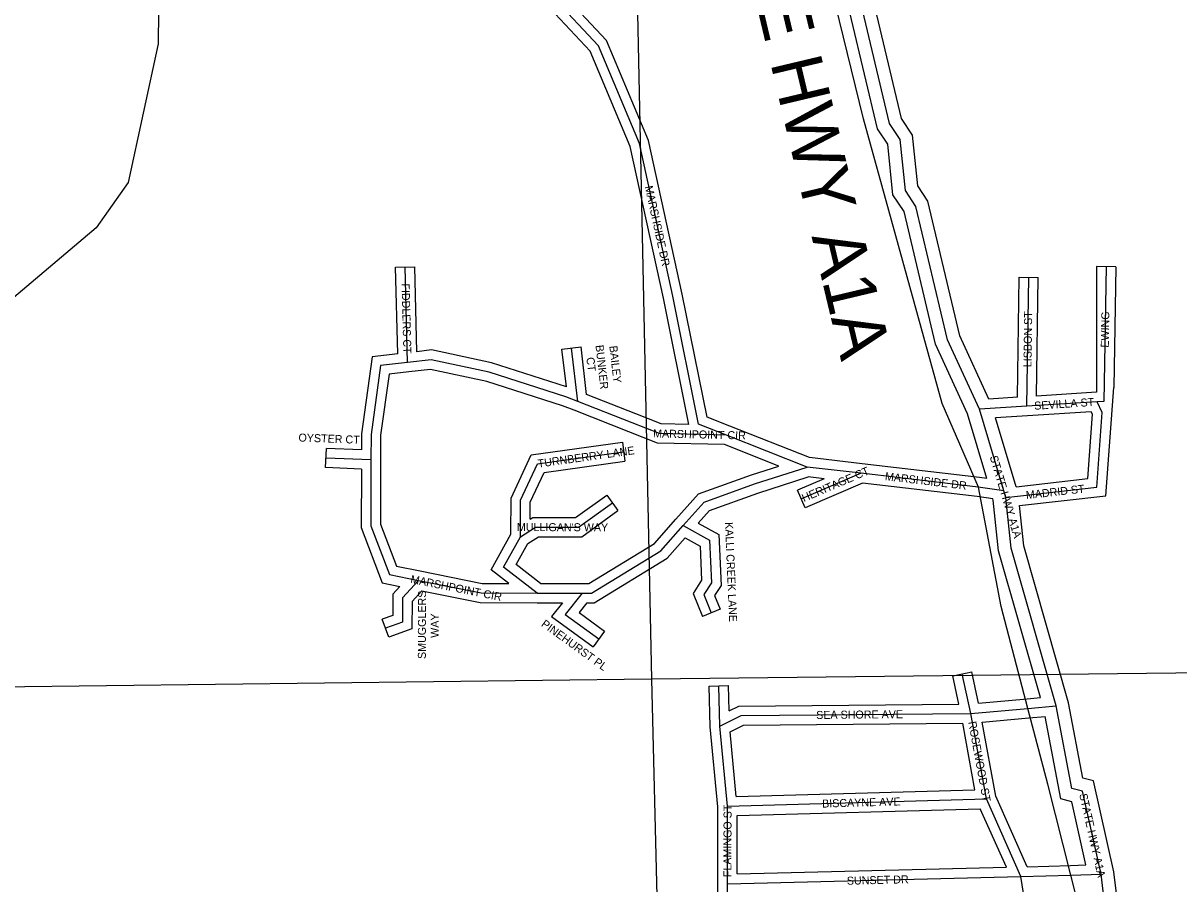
# Model space of a CAD drawing. Extents: x 418523 to 616617, y 1878279 to 2196743.
# Drawn here: x 566432 to 570042, y 1997576 to 2000265 of the extents above; entities that cross this region are included whole.
import ezdxf

# ---------------------------------------------------------------- set-up
doc = ezdxf.new("R2010")
doc.units = 0
for name, color, linetype in [('Level 1', 7, 'Continuous'), ('Level 22', 7, 'Continuous'), ('Level 23', 7, 'Continuous'), ('Level 28', 7, 'Continuous'), ('Level 31', 7, 'Continuous'), ('Level 32', 7, 'Continuous'), ('Level 34', 7, 'Continuous'), ('Level 7', 7, 'Continuous'), ('Level 8', 7, 'Continuous')]:
    doc.layers.add(name, color=color, linetype=linetype)

msp = doc.modelspace()

# ---------------------------------------------------------------- linework, layer by layer
at = {"layer": 'Level 1'}
for p, q in [((568285.081, 2003473.091), (568394.747, 1998215.331)), ((571360.308, 1998250.338), (568394.747, 1998215.331)), ((568394.747, 1998215.331), (565895.431, 1998185.226)), ((568394.747, 1998215.331), (568450.404, 1995887.192))]:
    msp.add_line(p, q, dxfattribs=at)
at = {"layer": 'Level 22'}
for p, q in [((569495.562, 1998804.097), (569419.427, 1999058.473)), ((569501.854, 1998782.99), (569495.562, 1998804.097))]:
    msp.add_line(p, q, dxfattribs=at)
for points in [[(569419.427, 1999058.473), (569319.74, 1999275.448), (569220.845, 1999692.434), (569187.669, 1999742.333), (569171.557, 1999900.926), (569138.383, 1999951.19), (568896.334, 2000970.005)], [(569658.55, 1998132.401), (569518.286, 1998624.396), (569501.854, 1998782.99)], [(569799.056, 1997606.586), (569741.319, 1997865.282), (569708.044, 1997873.725), (569658.55, 1998132.401)], [(569905.994, 1997097.943), (569848.391, 1997414.823), (569815.234, 1997473.45), (569799.056, 1997606.586)]]:
    msp.add_lwpolyline(points, dxfattribs=at)
at = {"layer": 'Level 23'}
for p, q in [((569442.467, 1998841.991), (569381.91, 1999044.318)), ((569533.513, 1998816.806), (569469.224, 1999031.601)), ((569462.453, 1998775.146), (569461.402, 1998778.673))]:
    msp.add_line(p, q, dxfattribs=at)
for points in [[(569448.773, 1999090.415), (569357.746, 1999288.541), (569258.116, 1999708.624), (569226.464, 1999756.231), (569210.359, 1999914.752), (569175.665, 1999967.319), (568935.251, 2000979.251)], [(569381.91, 1999044.319), (569281.734, 1999262.356), (569183.574, 1999676.244), (569148.874, 1999728.436), (569132.754, 1999887.099), (569101.1, 1999935.061), (568857.417, 2000960.759)], [(569609.661, 1998157.991), (569478.859, 1998616.795), (569462.453, 1998775.146)], [(569697.505, 1998141.661), (569557.714, 1998631.999), (569544.691, 1998757.691)], [(569838.528, 1997613.371), (569775, 1997898.005), (569742.549, 1997906.238), (569697.505, 1998141.661)], [(569751.714, 1997635.069), (569707.637, 1997832.56), (569673.539, 1997841.211), (569624.2, 1998099.081)], [(569944.724, 1997108.546), (569886.538, 1997428.63), (569853.979, 1997486.196), (569838.528, 1997613.371)]]:
    msp.add_lwpolyline(points, dxfattribs=at)
at = {"layer": 'Level 31'}
for p, q in [((567633, 1999204.931), (567625.158, 1999503.149)), ((569567.211, 1999067.942), (569572.918, 1999471.225)), ((568164.144, 1999083.282), (568144.883, 1999249.884)), ((568334.575, 1999016.325), (568164.144, 1999083.282)), ((569567.211, 1999067.942), (569419.427, 1999058.473)), ((569786.351, 1999082.336), (569567.211, 1999067.942)), ((569802.761, 1999048.841), (569786.351, 1999082.336)), ((569785.407, 1998815.414), (569802.761, 1999048.841)), ((568880.588, 1998878.286), (568628.741, 1998978.165)), ((567518.434, 1998900.826), (567377.977, 1998906.257)), ((569049.231, 1998858.611), (568880.588, 1998878.286)), ((569049.231, 1998858.611), (568862.911, 1998778.686)), ((569415.365, 1998815.56), (569049.231, 1998858.611)), ((569495.562, 1998804.097), (569415.365, 1998815.56)), ((569501.854, 1998782.99), (569785.407, 1998815.414)), ((568037.775, 1998484.279), (568178.246, 1998483.941)), ((569391.817, 1998107.939), (569365.474, 1998232.371)), ((568608.183, 1998068.344), (568605.313, 1998194.54)), ((569391.817, 1998107.939), (569570.697, 1998124.244)), ((569570.697, 1998124.244), (569658.55, 1998132.401)), ((569440.972, 1997841.262), (569391.817, 1998107.939)), ((568632.321, 1997818.454), (568608.183, 1998068.344)), ((568632.321, 1997818.454), (569440.972, 1997841.262)), ((569548.849, 1997599.176), (569440.972, 1997841.262)), ((568631.746, 1997576.623), (568632.321, 1997818.454)), ((568631.091, 1997301.337), (568631.746, 1997576.623)), ((568631.746, 1997576.623), (569548.849, 1997599.176)), ((569548.849, 1997599.176), (569704.871, 1997603.536)), ((569589.779, 1997340.519), (569548.849, 1997599.176)), ((569704.871, 1997603.536), (569799.056, 1997606.586))]:
    msp.add_line(p, q, dxfattribs=at)
for points in [[(568628.741, 1998978.165), (568541.941, 1999012.556), (568461.086, 1999412.408), (568356.953, 1999888.684), (568228.949, 2000193.736), (567943.362, 2000499.166), (567704.252, 2000747.393), (567624.725, 2000771.586)], [(569814.612, 1999504.475), (569807.914, 1999082.648), (569786.351, 1999082.336)], [(567633, 1999204.931), (567548.314, 1999194.953), (567518.624, 1998979.74), (567518.434, 1998900.826)], [(568164.144, 1999083.282), (568127.079, 1999097.917), (567887.547, 1999174.861), (567706.268, 1999213.481), (567633, 1999204.931)], [(568628.741, 1998978.165), (568419.158, 1998983.029), (568334.575, 1999016.325)], [(567985.561, 1998660.414), (567985.835, 1998774.601), (568038.745, 1998888.663), (568307.725, 1998926.201)], [(567518.434, 1998900.826), (567517.937, 1998694.634), (567575.914, 1998542.486), (567666.558, 1998524.084)], [(568493.621, 1998695.199), (568558.799, 1998768.501), (568716.844, 1998825.219), (568880.588, 1998878.286)], [(567985.561, 1998660.414), (568032.563, 1998690.485), (568167.008, 1998690.162), (568272.463, 1998766.277)], [(568178.246, 1998483.941), (568207.419, 1998483.872), (568423.99, 1998616.451), (568493.621, 1998695.199)], [(568493.621, 1998695.199), (568575.955, 1998649.545), (568581.664, 1998516.432), (568558.112, 1998480.123), (568581.44, 1998422.974)], [(568037.775, 1998484.279), (567932.696, 1998565.263), (567985.561, 1998660.414)], [(567666.558, 1998524.084), (567616.644, 1998469.656), (567616.46, 1998393.651), (567563.778, 1998374.869)], [(567666.558, 1998524.084), (567862.425, 1998484.701), (568037.775, 1998484.279)], [(568178.246, 1998483.941), (568125.45, 1998417.519), (568230.542, 1998341.262)], [(568608.183, 1998068.344), (568674.853, 1998101.641), (569391.817, 1998107.939)]]:
    msp.add_lwpolyline(points, dxfattribs=at)
at = {"layer": 'Level 32'}
for p, q in [((567595.168, 1999502.36), (567655.149, 1999503.936)), ((567602.291, 1999231.521), (567595.168, 1999502.36)), ((567662.129, 1999238.533), (567655.149, 1999503.936)), ((569784.615, 1999504.951), (569785.151, 1999112.321)), ((569844.609, 1999503.998), (569784.615, 1999504.951)), ((569844.609, 1999503.998), (569838.614, 1999126.417)), ((569537.607, 1999096.106), (569542.92, 1999471.649)), ((569542.92, 1999471.649), (569602.916, 1999470.801)), ((569597.67, 1999100.008), (569602.916, 1999470.801)), ((568115.081, 1999246.438), (568174.685, 1999253.328)), ((568128.668, 1999128.918), (568115.081, 1999246.438)), ((568191.878, 1999104.618), (568174.685, 1999253.328)), ((568345.546, 1999044.247), (568191.878, 1999104.618)), ((569537.607, 1999096.106), (569448.773, 1999090.415)), ((569785.151, 1999112.321), (569597.67, 1999100.006)), ((569813.484, 1998788.427), (569838.614, 1999126.417)), ((568323.606, 1998988.401), (568153.174, 1999055.359)), ((569569.13, 1999038.002), (569469.224, 1999031.601)), ((569768.256, 1999051.081), (569569.178, 1999038.006)), ((569757.331, 1998842.398), (569772.241, 1999042.949)), ((569772.241, 1999042.949), (569768.257, 1999051.081)), ((568887.981, 1998907.627), (568639.8, 1999006.051)), ((568303.579, 1998955.915), (568311.871, 1998896.488)), ((568792.044, 1998881.126), (568622.675, 1998948.296)), ((567376.819, 1998876.278), (567379.137, 1998936.236)), ((567488.509, 1998932.006), (567379.137, 1998936.236)), ((567488.364, 1998871.964), (567376.819, 1998876.278)), ((569052.709, 1998888.409), (568887.982, 1998907.627)), ((569419.241, 1998845.311), (569052.735, 1998888.406)), ((568934.047, 1998841.844), (568851.085, 1998806.256)), ((568934.047, 1998841.844), (568883.613, 1998847.728)), ((569442.467, 1998841.991), (569419.241, 1998845.311)), ((569533.513, 1998816.806), (569757.331, 1998842.398)), ((568874.739, 1998751.115), (568851.085, 1998806.256)), ((569053.691, 1998827.879), (568874.739, 1998751.115)), ((569411.492, 1998785.807), (569053.691, 1998827.879)), ((568254.904, 1998790.604), (568290.021, 1998741.951)), ((569461.401, 1998778.674), (569411.492, 1998785.807)), ((569544.691, 1998757.691), (569813.484, 1998788.427)), ((568048.027, 1998514.254), (568178.319, 1998513.941)), ((568037.704, 1998454.278), (568116.197, 1998454.089)), ((568609.216, 1998434.311), (568553.665, 1998411.636)), ((567573.853, 1998346.611), (567553.703, 1998403.127)), ((568248.161, 1998365.544), (568212.923, 1998316.981)), ((569336.125, 1998226.158), (569394.825, 1998238.585)), ((569354.869, 1998137.616), (569336.125, 1998226.158)), ((569415.646, 1998140.236), (569394.825, 1998238.585)), ((568575.32, 1998193.856), (568635.305, 1998195.221)), ((568578.217, 1998066.557), (568575.32, 1998193.856)), ((568637.101, 1998116.321), (568635.305, 1998195.221)), ((569415.646, 1998140.236), (569567.974, 1998154.121)), ((569567.924, 1998154.116), (569609.661, 1998157.991)), ((569427.28, 1998081.046), (569573.42, 1998094.367)), ((569573.47, 1998094.372), (569624.199, 1998099.082)), ((568602.319, 1997817.043), (568578.216, 1998066.558)), ((568659.49, 1997849.231), (568640.028, 1998050.712)), ((569405.121, 1997870.262), (569366.883, 1998077.717)), ((569469.829, 1997850.211), (569427.28, 1998081.046)), ((568659.49, 1997849.231), (569405.121, 1997870.262)), ((569568.081, 1997629.726), (569469.829, 1997850.211)), ((568601.746, 1997576.695), (568602.319, 1997817.043)), ((568662.254, 1997789.285), (569421.744, 1997810.706)), ((569503.133, 1997628.061), (569421.744, 1997810.706)), ((568661.82, 1997607.372), (568662.254, 1997789.285)), ((568661.821, 1997607.372), (569503.133, 1997628.061)), ((569568.08, 1997629.725), (569704.033, 1997633.524)), ((569703.9, 1997633.521), (569751.715, 1997635.069)), ((568601.091, 1997301.408), (568601.746, 1997576.695))]:
    msp.add_line(p, q, dxfattribs=at)
for points in [[(568639.791, 1999006.055), (568568.122, 1999034.452), (568490.445, 1999418.586), (568385.677, 1999897.767), (568254.533, 2000210.301), (567965.124, 2000519.819), (567720.447, 2000773.825), (567657.345, 2000793.021)], [(568511.671, 1999010.889), (568431.728, 1999406.231), (568328.229, 1999879.601), (568203.364, 2000177.172), (567921.601, 2000478.514), (567688.057, 2000720.961), (567615.994, 2000742.886)], [(568128.668, 1999128.918), (567895.28, 1999203.888), (567707.693, 1999243.852), (567662.129, 1999238.534)], [(567602.291, 1999231.52), (567521.766, 1999222.033), (567488.629, 1998981.835), (567488.509, 1998932.006)], [(567636.511, 1999175.136), (567574.863, 1999167.873), (567548.62, 1998977.644), (567548.434, 1998900.754)], [(568153.125, 1999055.378), (568116.972, 1999069.653), (567879.814, 1999145.835), (567704.844, 1999183.111), (567636.478, 1999175.133)], [(568511.671, 1999010.889), (568425.185, 1999012.898), (568345.564, 1999044.241)], [(568622.675, 1998948.296), (568413.131, 1998953.161), (568323.587, 1998988.409)], [(567955.58, 1998668.221), (567955.85, 1998781.256), (568018.408, 1998916.117), (568303.579, 1998955.915)], [(567548.434, 1998900.754), (567547.951, 1998700.121), (567598.068, 1998568.601), (567672.526, 1998553.484)], [(568015.694, 1998715.306), (568015.82, 1998767.948), (568059.082, 1998861.21), (568311.871, 1998896.488)], [(568471.201, 1998715.134), (568541.464, 1998794.154), (568707.149, 1998853.614), (568792.044, 1998881.126)], [(567488.364, 1998871.965), (567487.923, 1998689.146), (567553.761, 1998516.371), (567608.574, 1998505.241)], [(568540.939, 1998703.265), (568576.135, 1998742.848), (568726.538, 1998796.823), (568883.613, 1998847.729)], [(568015.694, 1998715.306), (568023.819, 1998720.506), (568157.344, 1998720.186), (568254.904, 1998790.604)], [(568008.109, 1998639.223), (568041.306, 1998660.463), (568176.671, 1998660.138), (568290.021, 1998741.951)], [(568178.318, 1998513.942), (568198.998, 1998513.892), (568404.493, 1998639.691), (568471.146, 1998715.071)], [(568540.94, 1998703.265), (568605.209, 1998667.628), (568612.047, 1998508.145), (568591.812, 1998476.948), (568609.216, 1998434.311)], [(567949.427, 1998514.491), (567893.931, 1998557.262), (567955.58, 1998668.221)], [(568048.028, 1998514.255), (567971.461, 1998573.263), (568008.109, 1998639.223)], [(568192.697, 1998453.906), (568215.839, 1998453.851), (568443.489, 1998593.211), (568500.14, 1998657.279)], [(568500.14, 1998657.28), (568546.703, 1998631.461), (568551.28, 1998524.72), (568524.412, 1998483.297), (568553.665, 1998411.636)], [(567672.471, 1998553.496), (567865.448, 1998514.693), (567949.427, 1998514.491)], [(567608.574, 1998505.241), (567586.671, 1998481.36), (567586.51, 1998414.824), (567553.703, 1998403.127)], [(567677.233, 1998491.336), (567646.616, 1998457.951), (567646.411, 1998372.479), (567573.853, 1998346.611)], [(567677.234, 1998491.336), (567859.404, 1998454.707), (568037.704, 1998454.278)], [(568116.196, 1998454.088), (568082.46, 1998411.647), (568212.923, 1998316.981)], [(568192.697, 1998453.906), (568168.44, 1998423.39), (568248.161, 1998365.544)], [(568637.101, 1998116.32), (568667.653, 1998131.581), (569354.869, 1998137.616)], [(568640.027, 1998050.713), (568682.052, 1998071.703), (569366.882, 1998077.717)]]:
    msp.add_lwpolyline(points, dxfattribs=at)
at = {"layer": 'Level 7'}
msp.add_lwpolyline([(564066.224, 2001935.016), (564375.129, 2002075.752), (564968.157, 2002423.948), (565535.935, 2002705.551), (565811.33, 2002796.377), (566186.628, 2002845.183), (566444.597, 2002702.613), (566477.749, 2002644.161), (566485.561, 2002485.738), (566442.936, 2002194.101), (566441.564, 2001768.941), (566482.956, 2001677.11), (566765.706, 2001459.448), (566865.251, 2001309.066), (566853.321, 2000200.371), (566760.216, 1999767.17), (566659.727, 1999625.786), (566375.504, 1999384.946), (565966.408, 1999186.206)], dxfattribs=at)
at = {"layer": 'Level 8'}
msp.add_lwpolyline([(569834.687, 1997093.337), (569704.675, 1997603.347), (569632.668, 1997887.353), (569570.663, 1998124.358), (569486.654, 1998442.364), (569415.646, 1998815.371), (569302.639, 1999076.376), (569056.618, 1999966.393), (568794.592, 2001038.414), (568726.586, 2001267.418), (568409.552, 2002762.449), (568364.547, 2002988.453), (568333.539, 2003399.462), (568231.525, 2004031.476), (568114.508, 2004839.492), (567972.493, 2005518.506), (567893.484, 2005899.513), (567805.477, 2006199.519), (567771.474, 2006316.521)], dxfattribs=at)

# ---------------------------------------------------------------- texts
at = {"layer": 'Level 28'}
msp.add_text('STATE HWY A1A', height=160, rotation=283.363447, dxfattribs=at).set_placement((568592.234, 2000870.827))
at = {"layer": 'Level 34'}
for s, height, rotation, p in [('MARSHSIDE DR', 25, 282.332142, (568373.599, 1999754.031)), ('FIDDLERS CT', 25, 271.505483, (567614.014, 1999451.473)), ('LISBON ST', 25, 89.188342, (569581.439, 1999190.046)), ('EWING', 25, 89.089244, (569823.084, 1999250.848)), ('BUNKER', 25, 276.5935, (568219.62, 1999258.246)), ('BAILEY', 25, 276.5935, (568262.851, 1999255.921)), ('CT', 25, 276.5935, (568191.077, 1999219.761)), ('SEVILLA ST', 25, 3.757114, (569590.857, 1999056.97)), ('MARSHPOINT CIR', 25, 358.669628, (568399.44, 1998970.986)), ('OYSTER CT', 25, 357.784975, (567291.572, 1998958.105)), ('TURNBERRY LANE', 25, 7.944153, (568041.141, 1998876.38)), ('STATE HWY A1A', 25, 286.598364, (569450.941, 1998910.03)), ('HERITAGE CT', 25, 23.216997, (568870.689, 1998768.423)), ('MARSHSIDE DR', 25, 353.292953, (569122.92, 1998837.362)), ('MADRID ST', 25, 6.522667, (569565.724, 1998777.713)), ("MULLIGAN'S WAY", 25, 359.861731, (567974.243, 1998678.128)), ('KALLI CREEK LANE', 25, 272.454208, (568624.059, 1998705.664)), ('MARSHPOINT CIR', 25, 348.630319, (567640.214, 1998516.632)), ('SMUGGLERS', 25, 89.861, (567689.889, 1998278.47)), ('WAY', 25, 89.861, (567730.088, 1998344.594)), ('PINEHURST PL', 25, 324.033933, (568048.124, 1998383.024)), ('SEA SHORE AVE', 25, 0.502542, (568909.196, 1998091.202)), ('ROSEWOOD ST', 25, 280.442722, (569383.976, 1998081.52)), ('BISCAYNE AVE', 25, 1.6149, (568927.909, 1997814.288)), ('STATE HWY A1A', 24.99916, 282.580569, (569730.703, 1997855.471)), ('FLAMINGO ST', 25, 89.862581, (568644.291, 1997596.88)), ('SUNSET DR', 25, 1.407936, (569005.118, 1997573.304))]:
    msp.add_text(s, height=height, rotation=rotation, dxfattribs=at).set_placement(p)

doc.saveas('drawing.dxf')
